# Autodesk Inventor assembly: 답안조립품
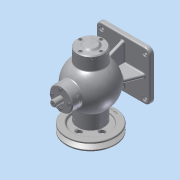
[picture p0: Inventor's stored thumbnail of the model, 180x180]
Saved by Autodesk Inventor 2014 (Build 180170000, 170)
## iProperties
Created: 2017-01
Part Number: 답안조립품
Document SubType Name: Assembly
Designer: ksu
Author: ksu
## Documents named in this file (19)
- C:\Users\ksu\Desktop\470118V1002\답안조립품.iam
- C:\Users\ksu\Desktop\470118V1002\1 본체.ipt
- C:\Users\ksu\Desktop\470118V1002\V-벨트풀리.ipt
- C:\Users\ksu\Desktop\470118V1002\너트 M8.ipt
- C:\Users\ksu\Desktop\470118V1002\뒤커버.ipt
- C:\Users\ksu\Desktop\470118V1002\멈춤링- 15 x 1.ipt
- C:\Users\ksu\Desktop\470118V1002\멈춤링- 35x1.6.ipt
- KS B 1336 - 35x1.6.ipt
- C:\Users\ksu\Desktop\470118V1002\베어링- 6202.ipt
- KS B 2023 - 6202 - 15 x 35 x 11 - 7.8.ipt
- C:\Users\ksu\Desktop\470118V1002\볼트 M4 x 12.ipt
- C:\Users\ksu\Desktop\470118V1002\볼트 M4 x 16.ipt
- C:\Users\ksu\Desktop\470118V1002\부시.ipt
- C:\Users\ksu\Desktop\470118V1002\상부커버.ipt
- C:\Users\ksu\Desktop\470118V1002\슬라이드.ipt
- C:\Users\ksu\Desktop\470118V1002\앞커버.ipt
- C:\Users\ksu\Desktop\470118V1002\오일실 15 30 7.ipt
- C:\Users\ksu\Desktop\470118V1002\키 4 x 4 x 12.ipt
- C:\Users\ksu\Desktop\470118V1002\편심축.ipt
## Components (17 placed, 6 different names)
1. 1 본체:1 — Insert:8, Insert:10, Insert:11, Insert:12, Mate:8, Mate:9, Mate:10
2. V-벨트풀리:1 — Mate:4, Mate:5, Mate:6
3. KS B 1336 - 35x1.6:1 — Insert:4, Insert:8
4. KS B 2023 - 6202 - 15 x 35 x 11 - 7.8:1 — Insert:7, Insert:9
5. KS B 2023 - 6202 - 15 x 35 x 11 - 7.8:2 — Insert:4, Insert:5
6. KS B 1021 - 에 따름 ISO 1207 - 미터 A  M 4 x 12:1 — Insert:14
7. KS B 1021 - 에 따름 ISO 1207 - 미터 A  M 4 x 12:2 — Insert:13, Mate:10
8. KS B 1021 - 에 따름 ISO 1207 - 미터 A  M 4 x 12:3 — Insert:16
9. KS B 1021 - 에 따름 ISO 1207 - 미터 A  M 4 x 12:4 — Insert:15
10. ISO 4762 M4 x 16:1 — Insert:18
11. ISO 4762 M4 x 16:2 — Insert:17
12. ISO 4762 M4 x 16:3 — Insert:19
13. ISO 4762 M4 x 16:4 — Insert:20, Mate:9
14. ISO 4762 M4 x 16:5 — Insert:23
15. ISO 4762 M4 x 16:6 — Insert:21
16. ISO 4762 M4 x 16:7 — Insert:22, Mate:8
17. ISO 4762 M4 x 16:8 — Insert:24
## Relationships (26: Insert 20, Mate 6)
- Mate:4: V-벨트풀리:1
- Mate:5: V-벨트풀리:1
- Mate:6: V-벨트풀리:1
- Insert:4: KS B 1336 - 35x1.6:1 ↔ KS B 2023 - 6202 - 15 x 35 x 11 - 7.8:2
- Insert:5: KS B 2023 - 6202 - 15 x 35 x 11 - 7.8:2
- Insert:7: KS B 2023 - 6202 - 15 x 35 x 11 - 7.8:1
- Insert:8: 1 본체:1 ↔ KS B 1336 - 35x1.6:1
- Insert:9: KS B 2023 - 6202 - 15 x 35 x 11 - 7.8:1
- Insert:10: 1 본체:1
- Insert:11: 1 본체:1
- Insert:12: 1 본체:1
- Insert:13: KS B 1021 - 에 따름 ISO 1207 - 미터 A  M 4 x 12:2
- Insert:14: KS B 1021 - 에 따름 ISO 1207 - 미터 A  M 4 x 12:1
- Insert:15: KS B 1021 - 에 따름 ISO 1207 - 미터 A  M 4 x 12:4
- Insert:16: KS B 1021 - 에 따름 ISO 1207 - 미터 A  M 4 x 12:3
- Insert:17: ISO 4762 M4 x 16:2
- Insert:18: ISO 4762 M4 x 16:1
- Insert:19: ISO 4762 M4 x 16:3
- Insert:20: ISO 4762 M4 x 16:4
- Insert:21: ISO 4762 M4 x 16:6
- Insert:22: ISO 4762 M4 x 16:7
- Insert:23: ISO 4762 M4 x 16:5
- Insert:24: ISO 4762 M4 x 16:8
- Mate:8: 1 본체:1 ↔ ISO 4762 M4 x 16:7
- Mate:9: 1 본체:1 ↔ ISO 4762 M4 x 16:4
- Mate:10: 1 본체:1 ↔ KS B 1021 - 에 따름 ISO 1207 - 미터 A  M 4 x 12:2
